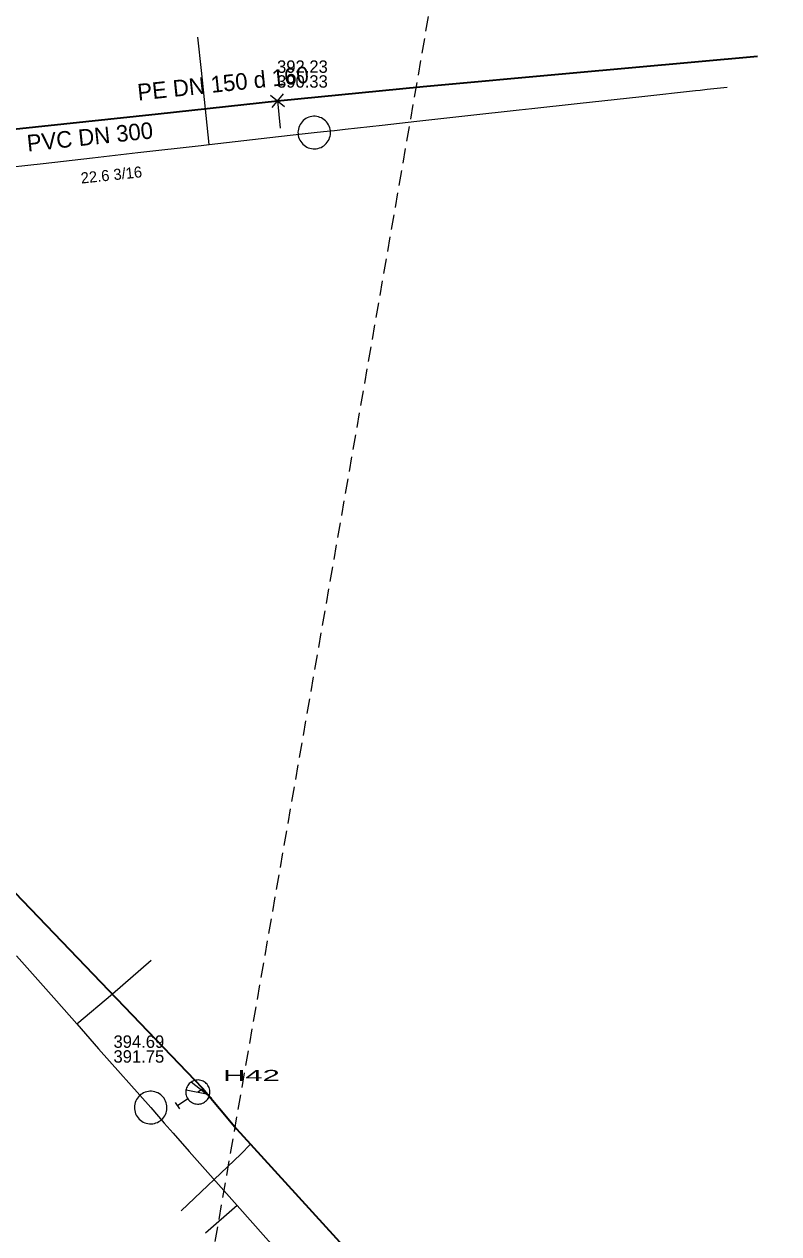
# Model space of a CAD drawing. Extents: x -772952 to -772403, y -1033777 to -1033210.
# Drawn here: x -772593.4 to -772538.7, y -1033421 to -1033333.3 of the extents above; entities that cross this region are included whole.
import ezdxf

# ---------------------------------------------------------------- set-up
doc = ezdxf.new("R2010")
doc.units = 0
doc.header["$LTSCALE"] = 0.36
doc.linetypes.add('MEDIUM_DASHED', pattern=[4.5, 3, -1.5])
for name, color, linetype, lineweight in [('15', 7, 'Continuous', 13), ('16', 7, 'Continuous', 35), ('2', 7, 'Continuous', 25), ('20', 7, 'Continuous', 13), ('4', 7, 'Continuous', 13), ('57', 7, 'Continuous', 13), ('59', 7, 'Continuous', 13), ('62', 7, 'MEDIUM_DASHED', 25)]:
    doc.layers.add(name, color=color, linetype=linetype, lineweight=lineweight)
for name, color, linetype in [('17', 7, 'Continuous'), ('3', 7, 'Continuous'), ('6', 7, 'Continuous')]:
    doc.layers.add(name, color=color, linetype=linetype)

msp = doc.modelspace()

# ---------------------------------------------------------------- linework, layer by layer
at = {"layer": '15'}
for p, q in [((-772575.563, -1033338.41), (-772574.553, -1033339.231)), ((-772574.653, -1033338.32), (-772575.469, -1033339.32)), ((-772581.314, -1033409.97), (-772579.85, -1033411.122))]:
    msp.add_line(p, q, dxfattribs=at)
at = {"layer": '16'}
for points in [[(-772611.91, -1033342.769), (-772603.55, -1033342.1), (-772594.219, -1033340.89), (-772583.71, -1033339.769), (-772575.059, -1033338.82), (-772564.48, -1033337.789), (-772553.859, -1033336.829), (-772540.23, -1033335.589)], [(-772612.278, -1033377.333), (-772580.497, -1033410.436), (-772578.041, -1033413.37), (-772577.006, -1033414.5), (-772569.058, -1033423.229), (-772559.875, -1033433.313), (-772549.379, -1033444.412), (-772529.995, -1033467.089), (-772529.738, -1033467.366), (-772517.883, -1033480.75), (-772495.067, -1033506.688), (-772494.015, -1033507.864), (-772482.842, -1033520.835)]]:
    msp.add_lwpolyline(points, dxfattribs=at)
at = {"layer": '2'}
for points in [[(-772572.39, -1033341.13), (-772571.708, -1033341.054), (-772570.929, -1033340.969), (-772570.152, -1033340.883), (-772567.459, -1033340.586), (-772564.957, -1033340.311), (-772561.244, -1033339.902), (-772557.511, -1033339.491), (-772556.597, -1033339.39), (-772553.315, -1033339.028), (-772548.613, -1033338.511), (-772544.729, -1033338.083), (-772544.375, -1033338.044), (-772543.881, -1033337.989), (-772542.43, -1033337.83)], [(-772601.82, -1033344.47), (-772600.191, -1033344.285), (-772599.257, -1033344.179), (-772595.643, -1033343.769), (-772592.064, -1033343.362), (-772588.473, -1033342.955), (-772585.192, -1033342.582), (-772580.597, -1033342.061), (-772580.014, -1033341.995), (-772575.604, -1033341.494), (-772574.126, -1033341.327), (-772572.39, -1033341.13)], [(-772593.987, -1033400.841), (-772592.452, -1033402.577), (-772591.102, -1033404.103), (-772589.629, -1033405.769), (-772588.037, -1033407.569), (-772584.26, -1033411.84)], [(-772584.26, -1033411.84), (-772583.281, -1033412.97), (-772582.626, -1033413.707), (-772581.458, -1033415.024), (-772577.989, -1033418.933), (-772574.948, -1033422.36), (-772572.179, -1033425.48), (-772568.334, -1033429.813), (-772566.069, -1033432.365), (-772562.501, -1033436.385), (-772560.333, -1033438.828), (-772558.052, -1033441.399), (-772556.944, -1033442.647), (-772555.536, -1033444.234), (-772553.815, -1033446.173), (-772551.058, -1033449.281)]]:
    msp.add_lwpolyline(points, dxfattribs=at)
at = {"layer": '20'}
for p, q in [((-772581.69, -1033410.548), (-772579.974, -1033410.889)), ((-772582.154, -1033411.927), (-772582.454, -1033411.477)), ((-772581.568, -1033411.211), (-772582.304, -1033411.702))]:
    msp.add_line(p, q, dxfattribs=at)
msp.add_lwpolyline([(-772581.321, -1033409.988), (-772581.394, -1033410.041), (-772581.461, -1033410.103), (-772581.523, -1033410.173), (-772581.575, -1033410.246), (-772581.62, -1033410.327), (-772581.657, -1033410.412), (-772581.683, -1033410.499), (-772581.702, -1033410.589), (-772581.708, -1033410.68), (-772581.708, -1033410.77), (-772581.697, -1033410.862), (-772581.678, -1033410.952), (-772581.649, -1033411.039), (-772581.61, -1033411.122), (-772581.563, -1033411.2), (-772581.508, -1033411.275), (-772581.447, -1033411.342), (-772581.378, -1033411.401), (-772581.302, -1033411.454), (-772581.221, -1033411.499), (-772581.137, -1033411.534), (-772581.051, -1033411.563), (-772580.96, -1033411.58), (-772580.87, -1033411.589), (-772580.777, -1033411.587), (-772580.686, -1033411.577), (-772580.598, -1033411.557), (-772580.51, -1033411.527), (-772580.428, -1033411.488), (-772580.348, -1033411.442), (-772580.276, -1033411.387), (-772580.209, -1033411.325), (-772580.148, -1033411.256), (-772580.096, -1033411.182), (-772580.051, -1033411.102), (-772580.014, -1033411.017), (-772579.988, -1033410.93), (-772579.968, -1033410.84), (-772579.962, -1033410.749), (-772579.962, -1033410.658), (-772579.973, -1033410.566), (-772579.992, -1033410.476), (-772580.023, -1033410.391), (-772580.06, -1033410.307), (-772580.107, -1033410.228), (-772580.162, -1033410.154), (-772580.225, -1033410.088), (-772580.292, -1033410.027), (-772580.368, -1033409.974), (-772580.449, -1033409.93), (-772580.533, -1033409.894), (-772580.619, -1033409.865), (-772580.71, -1033409.849), (-772580.8, -1033409.839), (-772580.893, -1033409.841), (-772580.984, -1033409.852), (-772581.072, -1033409.872), (-772581.16, -1033409.902), (-772581.243, -1033409.94), (-772581.32, -1033409.987)], dxfattribs=at)
at = {"layer": '4'}
for points in [[(-772571.21, -1033341.13), (-772571.216, -1033341.011), (-772571.234, -1033340.894), (-772571.263, -1033340.778), (-772571.304, -1033340.667), (-772571.356, -1033340.56), (-772571.419, -1033340.459), (-772571.492, -1033340.364), (-772571.573, -1033340.278), (-772571.663, -1033340.2), (-772571.761, -1033340.131), (-772571.864, -1033340.073), (-772571.973, -1033340.026), (-772572.087, -1033339.989), (-772572.203, -1033339.964), (-772572.321, -1033339.952), (-772572.44, -1033339.951), (-772572.559, -1033339.962), (-772572.675, -1033339.985), (-772572.789, -1033340.019), (-772572.899, -1033340.065), (-772573.004, -1033340.122), (-772573.102, -1033340.189), (-772573.193, -1033340.265), (-772573.276, -1033340.35), (-772573.35, -1033340.444), (-772573.414, -1033340.544), (-772573.468, -1033340.65), (-772573.511, -1033340.761), (-772573.543, -1033340.875), (-772573.562, -1033340.993), (-772573.57, -1033341.112), (-772573.566, -1033341.23), (-772573.55, -1033341.348), (-772573.522, -1033341.464), (-772573.483, -1033341.576), (-772573.432, -1033341.684), (-772573.371, -1033341.786), (-772573.3, -1033341.882), (-772573.22, -1033341.969), (-772573.131, -1033342.049), (-772573.035, -1033342.119), (-772572.932, -1033342.179), (-772572.824, -1033342.228), (-772572.711, -1033342.266), (-772572.595, -1033342.292), (-772572.477, -1033342.307), (-772572.358, -1033342.31), (-772572.24, -1033342.301), (-772572.122, -1033342.28), (-772572.008, -1033342.247), (-772571.898, -1033342.203), (-772571.792, -1033342.148), (-772571.693, -1033342.082), (-772571.6, -1033342.007), (-772571.516, -1033341.923), (-772571.441, -1033341.831), (-772571.375, -1033341.732), (-772571.319, -1033341.627), (-772571.275, -1033341.517), (-772571.241, -1033341.403), (-772571.22, -1033341.286), (-772571.21, -1033341.167)], [(-772583.08, -1033411.84), (-772583.086, -1033411.721), (-772583.104, -1033411.604), (-772583.133, -1033411.488), (-772583.174, -1033411.377), (-772583.226, -1033411.27), (-772583.289, -1033411.169), (-772583.362, -1033411.074), (-772583.443, -1033410.988), (-772583.533, -1033410.91), (-772583.631, -1033410.841), (-772583.734, -1033410.783), (-772583.843, -1033410.736), (-772583.957, -1033410.699), (-772584.073, -1033410.674), (-772584.191, -1033410.662), (-772584.31, -1033410.661), (-772584.429, -1033410.672), (-772584.545, -1033410.695), (-772584.659, -1033410.729), (-772584.769, -1033410.775), (-772584.874, -1033410.832), (-772584.972, -1033410.899), (-772585.063, -1033410.975), (-772585.146, -1033411.06), (-772585.22, -1033411.154), (-772585.284, -1033411.254), (-772585.338, -1033411.36), (-772585.381, -1033411.471), (-772585.413, -1033411.585), (-772585.432, -1033411.703), (-772585.44, -1033411.822), (-772585.436, -1033411.94), (-772585.42, -1033412.058), (-772585.392, -1033412.174), (-772585.353, -1033412.286), (-772585.302, -1033412.394), (-772585.241, -1033412.496), (-772585.17, -1033412.592), (-772585.09, -1033412.679), (-772585.001, -1033412.759), (-772584.905, -1033412.829), (-772584.802, -1033412.889), (-772584.694, -1033412.938), (-772584.581, -1033412.976), (-772584.465, -1033413.002), (-772584.347, -1033413.017), (-772584.228, -1033413.02), (-772584.11, -1033413.011), (-772583.992, -1033412.99), (-772583.878, -1033412.957), (-772583.768, -1033412.913), (-772583.662, -1033412.858), (-772583.563, -1033412.792), (-772583.47, -1033412.717), (-772583.386, -1033412.633), (-772583.311, -1033412.541), (-772583.245, -1033412.442), (-772583.189, -1033412.337), (-772583.145, -1033412.227), (-772583.111, -1033412.113), (-772583.09, -1033411.996), (-772583.08, -1033411.877)]]:
    msp.add_lwpolyline(points, close=True, dxfattribs=at)
at = {"layer": '57'}
msp.add_line((-772577.989, -1033418.933), (-772580.27, -1033420.95), dxfattribs=at)
for points in [[(-772580.014, -1033341.995), (-772580.571, -1033336.62), (-772580.83, -1033334.22)], [(-772589.629, -1033405.769), (-772587.04, -1033403.6), (-772584.23, -1033401.16)]]:
    msp.add_lwpolyline(points, dxfattribs=at)
at = {"layer": '59'}
msp.add_line((-772575.059, -1033338.82), (-772574.853, -1033340.809), dxfattribs=at)
for points in [[(-772580.497, -1033410.437), (-772580.583, -1033410.546), (-772580.836, -1033410.715)], [(-772577.007, -1033414.5), (-772577.727, -1033415.218), (-772582.044, -1033419.322)]]:
    msp.add_lwpolyline(points, dxfattribs=at)
at = {"layer": '62'}
msp.add_lwpolyline([(-772641.514, -1033776.98), (-772641.529, -1033776.987), (-772951.708, -1033584.106), (-772846.395, -1033249.938), (-772562.451, -1033323.146)], close=True, dxfattribs=at)

# ---------------------------------------------------------------- texts
at = {"layer": '17'}
msp.add_text('PE DN 150 d 160 ', height=1.2, rotation=6, dxfattribs=at).set_placement((-772585.157, -1033338.813))
at = {"layer": '20', "width": 2.1}
msp.add_text('H42 ', height=0.8, dxfattribs=at).set_placement((-772579.01, -1033409.91))
at = {"layer": '3'}
for s, height, p in [('PVC DN 300', 1.2, (-772593.176, -1033342.508)), ('22.6 3/16', 0.8, (-772589.289, -1033344.833))]:
    msp.add_text(s, height=height, rotation=6, dxfattribs=at).set_placement(p)
at = {"layer": '6'}
for s, p in [('392.23', (-772575.088, -1033336.798)), ('390.33', (-772575.088, -1033337.875)), ('394.69', (-772586.958, -1033407.507)), ('391.75', (-772586.958, -1033408.584))]:
    msp.add_text(s, height=0.9, dxfattribs=at).set_placement(p)

doc.saveas('drawing.dxf')
